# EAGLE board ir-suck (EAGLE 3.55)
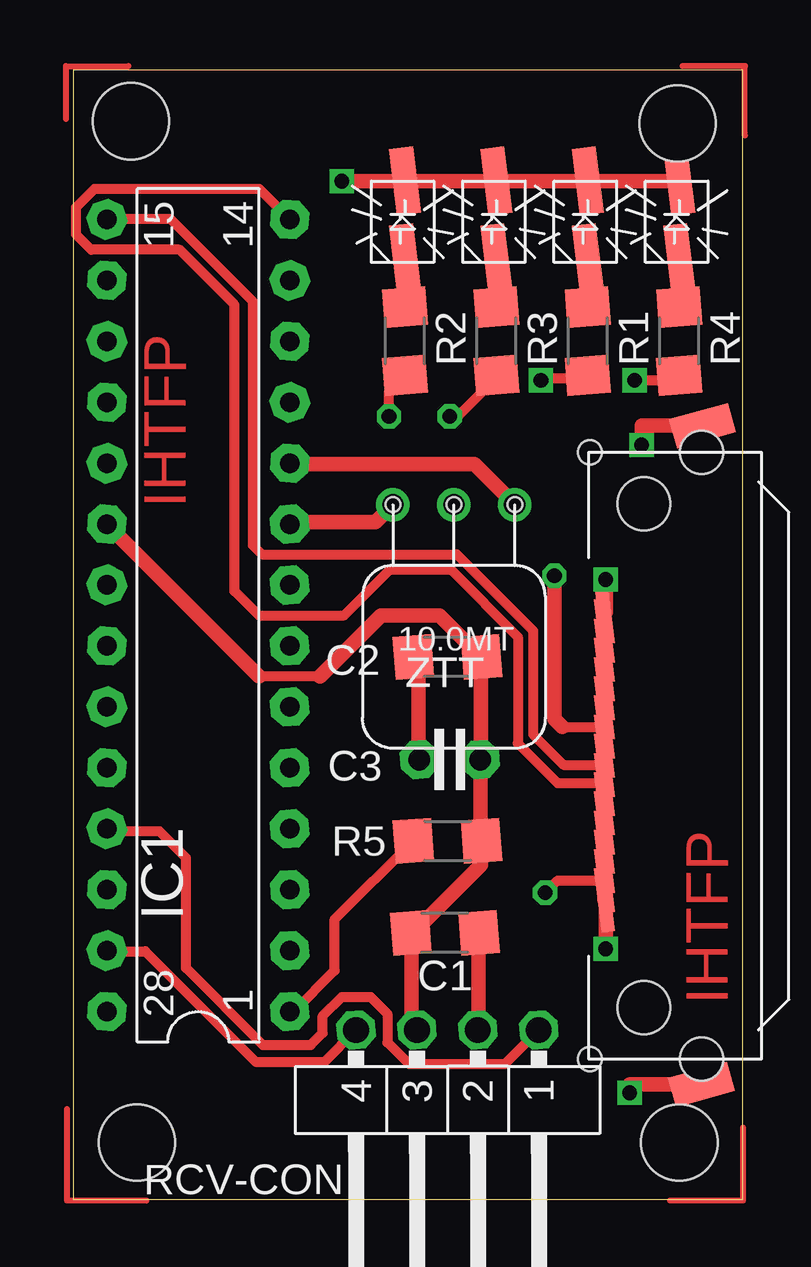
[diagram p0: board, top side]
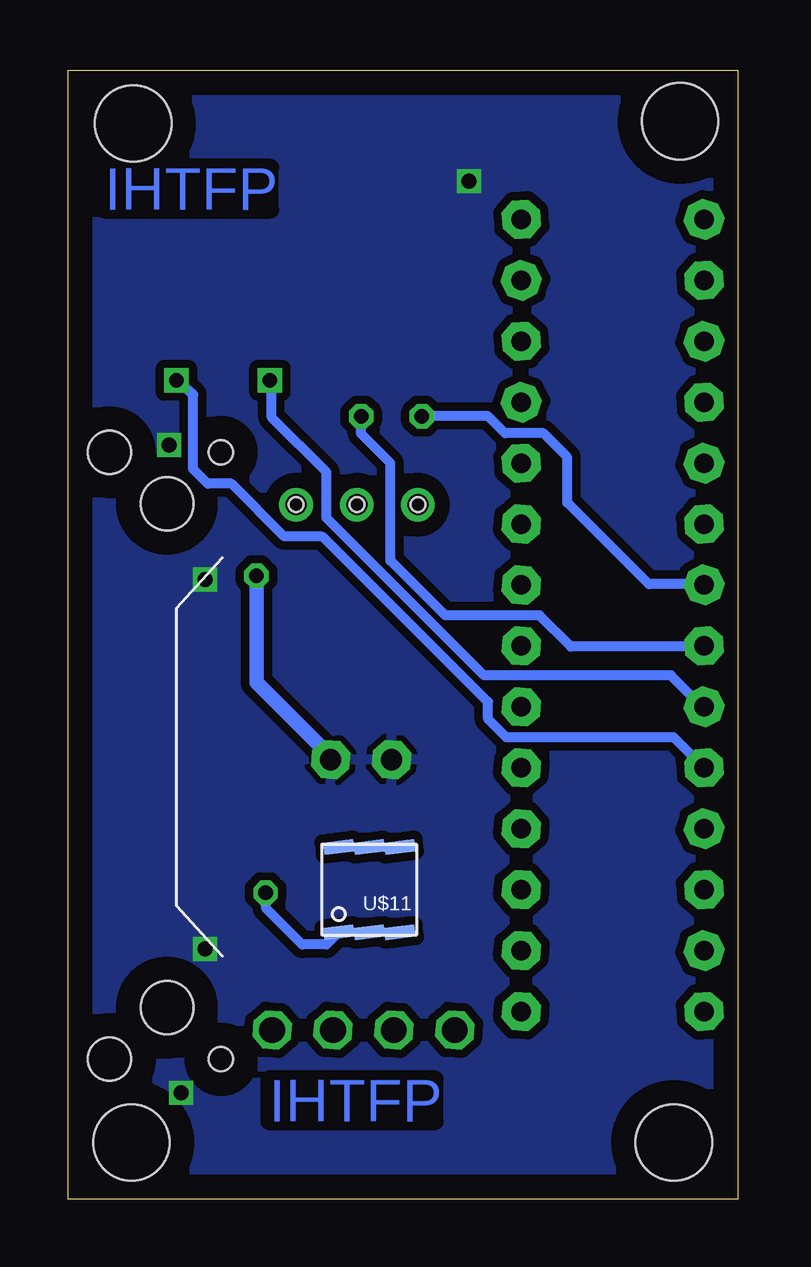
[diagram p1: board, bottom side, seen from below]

Size 27.92 x 47.07 mm. Coordinates in mm from the lower left corner, seen from the top.
Outline: 0,0 27.92,0 27.92,47.07 0,47.07 0,0
Copper layers used: Top, Bottom
Holes 3.17 mm at 25.2,44.85 2.4,44.95 25.27,2.38 2.66,2.38

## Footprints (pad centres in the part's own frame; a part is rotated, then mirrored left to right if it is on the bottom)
T10 = drill 0.889 pad 1.397 round:  -2.54,0;  0,0;  2.54,0 | hole 0.61: 0,0; -2.54,0; 2.54,0
206 = smd 1.6 x 1.803 rotated 4.4:  1.422,0 | smd 1.6 x 1.803 rotated 4.3:  -1.422,0
2,5 = drill 0.889 pad 1.6 octagon:  -1.27,0;  1.27,0
L28-3 = drill 0.813 pad 1.6 octagon:  -16.51,-3.81;  -13.97,-3.81;  -11.43,-3.81;  -8.89,-3.81;  -6.35,-3.81;  -3.81,-3.81;  -1.27,-3.81;  1.27,-3.81;  3.81,-3.81;  6.35,-3.81;  8.89,-3.81;  11.43,-3.81;  13.97,-3.81;  16.51,-3.81;  16.51,3.81;  13.97,3.81;  11.43,3.81;  8.89,3.81;  6.35,3.81;  3.81,3.81;  1.27,3.81;  -1.27,3.81;  -3.81,3.81;  -6.35,3.81;  -8.89,3.81;  -11.43,3.81;  -13.97,3.81;  -16.51,3.81
2711CT = smd 1 x 2.8 rotated 97:  -1.6,0;  1.6,0
04-WS = drill 1.067 pad 1.6 octagon:  -3.81,-2.54;  -6.35,-2.54;  -8.89,-2.54;  -11.43,-2.54
OC6 = smd 0.508 x 1.27 rotated 97:  0,1.778;  1.27,1.778;  -1.27,1.778;  0,-1.778;  -1.27,-1.778;  1.27,-1.778
S3500 = smd 0.55 x 2.7 rotated 97: 0 -1.2,1.35; 1 -2,1.35; 2 -2.8,1.35; 3 -3.6,1.35; 4 -4.4,1.35; 5 -5.2,1.35; 6 -6,1.35;  6,1.35;  5.2,1.35;  4.4,1.35;  3.6,1.35;  2.8,1.35;  2,1.35;  1.2,1.35;  0.4,1.35;  -0.4,1.35 | smd 1.27 x 2.54 rotated 344.5: ND1 -13.7,-2.7; ND2 13.76,-2.74 | hole 2.2: -10.5,-0.3; 10.5,-0.3 | hole 1.8: -12.65,-2.7; 12.65,-2.7 | hole 1: -12.65,1.95; 12.65,1.95

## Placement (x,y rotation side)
10MHZ  ZTT10MHZ  [T10]  15.87,28.97 180 top
C1  0.1uF  [206]  15.5,11.12 0 top
C2  0.1uF  [206]  15.6,22.62 0 top
C3  33uF  [2,5]  15.7,18.34 180 top
IC1  16C76JW  [L28-3]  5.21,24.35 90 top
L1  L62711CTND  [2711CT]  21.45,40.86 90 top
L2  L62711CTND  [2711CT]  13.83,40.86 90 top
L3  L62711CTND  [2711CT]  17.64,40.86 90 top
L5  L62711CTND  [2711CT]  25.26,40.86 90 top
R1  1k  [206]  21.45,35.78 270 top
R2  1k  [206]  13.83,35.78 270 top
R3  1k  [206]  17.64,35.78 270 top
R4  1k  [206]  25.26,35.78 270 top
R5  5k  [206]  15.6,14.96 180 top
RCV-CON  MA04-WS  [04-WS]  7.98,4.53 180 top
U$11  DS2401P  [OC6]  15.36,12.92 180 bottom
U$41  HRS3500R  [S3500]  23.49,18.5 90 top

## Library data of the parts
10MHZ C3 L1-L3 L5 RCV-CON U$11 U$41 = evilb0rg
C1 C2 R1-R5 = ipc-rcl
IC1 = pic

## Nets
1WIRE: U$11. U$41.5
+5V: C1. C2. C3. IC1. R5. RCV-CON. U$41.
BSEDCIN: U$41.
EXP_1: U$41.
EXP_2: U$41.
EXP_3: U$41.1
EXP_4: U$41.2
EXP_5: U$41.3
EXP_6: U$41.4
GND1: 10MHZ. C1. C2. C3. IC1. L1. L2. L3. L5. RCV-CON. U$11. U$41. U$41.6 U$41.ND1 U$41.ND2
I2CSCL: IC1. U$41.0
I2CSDA: IC1. U$41.
IR_RCV: IC1. RCV-CON.
IR_RCV2: IC1. RCV-CON.
N$1: 10MHZ. IC1.
N$2: 10MHZ. IC1.
N$3: L1. R1.
N$4: L3. R3.
N$5: L2. R2.
N$6: L5. R4.
N$7: IC1. R5.
RED_LED: IC1. R1.
STAT1: IC1. R2.
STAT2: IC1. R3.
STAT3: IC1. R4.
USB+5V: U$41.
USBD+: U$41.
USBD-: U$41.

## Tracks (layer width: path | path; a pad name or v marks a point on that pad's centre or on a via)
1WIRE  (via drill 0.61 pad 1.02)
  Top 0.406: U$41.5 20.19,13.3 v19.68,12.79
  Bottom 0.406: v19.68,12.79 19.65,12.76 19.65,12.13 18.16,10.63 17.14,10.63 16.63,11.14
+5V  (via drill 0.61 pad 1.02)
  Top 0.406: 10.28,21.81 7.74,21.81 | 20.39,19.7 22.14,19.7
  Top 0.61: 17.1,22.55 17.03,22.62 17,22.62 | 17,22.62 v17,18.45 16.9,18.35 16.91,18.34 16.97,18.34 16.97,14.98 17,14.95 | 17,14.95 R5. | 17,14.95 17,13.95 14.1,11.05 14.1,11.12 14.1,7.15 14.3,6.95 14.33,6.98 14.33,7.07 | 17,22.62 15.27,24.35 12.82,24.35 10.28,21.81 | 1.4,28.16 1.4,28.15 7.74,21.81 | 20.39,19.7 20.06,20.03 v20.06,26
  Bottom 0.61: 16.95,18.45 16.89,18.38 | v17,18.45 16.95,18.45 | v20.06,26 20.06,21.55 16.95,18.45
GND1  (via drill 0.61 pad 1.02)
  Top 0.61: L1. L5. | L1. 21.2,42.46 21.2,42.45 | L3. L1. | L3. 17.2,42.46 17.2,42.45 | L2. L3. | L2. 13.7,42.46 13.7,42.45 | L2. v11.2,42.46 v11.2,42.45 | U$41.ND2 23.7,32.26 v23.7,31.45 | U$41.ND1 23.2,4.8 v23.2,4.45 | 22.14,24.5 22.2,24.5 v22.2,25.85 | U$41.6 22.2,12.5 v22.2,10.45 | 16.87,7.07 16.87,7.08 16.8,7.15 16.9,7.25 16.9,11.12 | C3. 14.4,18.35 14.4,22.42 14.2,22.62
  pour Bottom (isolate 0.356): -0.1,47.15 27.9,47.15 27.9,0.06 -0.2,0.06 -0.2,47.25
I2CSCL
  Top 0.406: 9.02,40.86 7.75,42.13 0.88,42.13 0.12,41.36 0.12,40.22 0.76,39.59 4.44,39.59 6.73,37.3 6.73,25.36 7.74,24.35 11.3,24.35 13.2,26.25 15.74,26.25 18.54,23.46 18.54,19.01 20.19,17.36 22.09,17.36 22.09,17.34 U$41.0
I2CSDA
  Top 0.406: 22.1,18.06 22.1,18.05 | 22.1,18.06 U$41. | 1.4,40.86 4.06,40.86 7.49,37.43 7.49,27.27 7.87,26.89 16,26.89 19.17,23.71 19.17,19.39 20.44,18.12 22.09,18.12 22.09,18.06 22.1,18.06
IR_RCV
  Top 0.406: RCV-CON. 17.99,5.65 14,5.65 13.1,6.55 13.1,7.75 12.4,8.45 11.2,8.45 10.4,7.65 10.4,6.95 9.9,6.45 7.9,6.45 4.7,9.65 4.7,14.25 3.6,15.35 1.3,15.35 1.3,15.36 1.4,15.46
IR_RCV2
  Top 0.406: 11.79,7.07 10.47,5.75 7.6,5.75 3,10.35 1.4,10.35 1.4,10.38
N$1
  Top 0.61: 9.02,28.16 9,28.18 9,28.25 12.61,28.25 10MHZ.
N$2
  Top 0.61: 8.97,30.65 8.9,30.65 | 9.02,30.7 8.97,30.65 | 18.41,28.97 16.73,30.65 8.97,30.65
N$3
  Top 0.406: 21.4,39.31 21.4,39.35 | 21.45,39.26 21.4,39.31 | R1. 21.4,37.25 21.4,39.31
N$4
  Top 0.406: 17.6,39.3 17.6,39.35 | 17.64,39.26 17.6,39.3 | R3. 17.6,37.24 17.6,39.3
N$5
  Top 0.406: 13.8,39.29 13.8,39.35 | 13.83,39.26 13.8,39.29 | R2. 13.8,37.23 13.8,39.29
N$6
  Top 0.406: 25.26,39.26 25.25,39.25 25.1,39.25 25.2,39.15 25.2,37.26 R4.
N$7
  Top 0.406: 14.18,14.96 10.9,11.68 10.9,9.55 9.2,7.85 9.01,7.85 | 9.01,7.85 8.9,7.85 | 9.02,7.84 9.01,7.85
N$8
  Top 0.254: -0.3,45.05 -0.3,47.25 2.3,47.25
N$9
  Top 0.254: 28,44.35 28,47.25 25.4,47.25
N$10
  Top 0.254: 27.93,3.01 27.93,-0.04 24.89,-0.04
N$11
  Top 0.254: -0.26,3.77 -0.26,-0.04 3.04,-0.04
RED_LED  (via drill 0.61 pad 1.02)
  Top 0.406: 21.45,34.35 21.34,34.25 19.6,34.25 v19.5,34.15
  Bottom 0.406: 1.4,20.54 1.47,20.54 2.79,21.85 10.58,21.85 17.14,28.41 17.14,30.32 19.43,32.6 19.43,34.12 19.45,34.15 v19.5,34.15
STAT1  (via drill 0.61 pad 1.02)
  Top 0.406: 13.83,34.37 13.84,34.38 | 13.83,34.37 13.83,34.35 | v13.16,32.65 13.16,33.71 13.83,34.37
  Bottom 0.406: 1.4,25.62 1.4,25.65 3.7,25.65 7.1,29.05 7.1,30.95 8.1,31.95 9.7,31.95 10.4,32.65 v13.16,32.65
STAT2  (via drill 0.61 pad 1.02)
  Top 0.406: 17.64,34.35 17.6,34.31 17.6,34.3 17.65,34.25 16.04,32.65 v15.7,32.65
  Bottom 0.406: 1.4,23.08 1.4,23.05 6.96,23.05 8.26,24.35 12.19,24.35 14.47,26.63 14.47,30.7 15.7,31.92 v15.7,32.65
STAT3  (via drill 0.61 pad 1.02)
  Top 0.406: 25.26,34.35 25.26,34.31 25.1,34.15 v23.4,34.15
  Bottom 0.406: v23.4,34.15 22.7,33.55 22.7,30.45 22.09,29.84 21.11,29.84 18.91,27.64 17.4,27.64 17.27,27.61 10.41,20.74 10.41,20.03 9.65,19.27 2.66,19.27 1.52,18.12 1.39,18.12 1.39,18 1.4,18

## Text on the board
Top: IHTFP | IHTFP
Bottom: IHTFP | IHTFP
